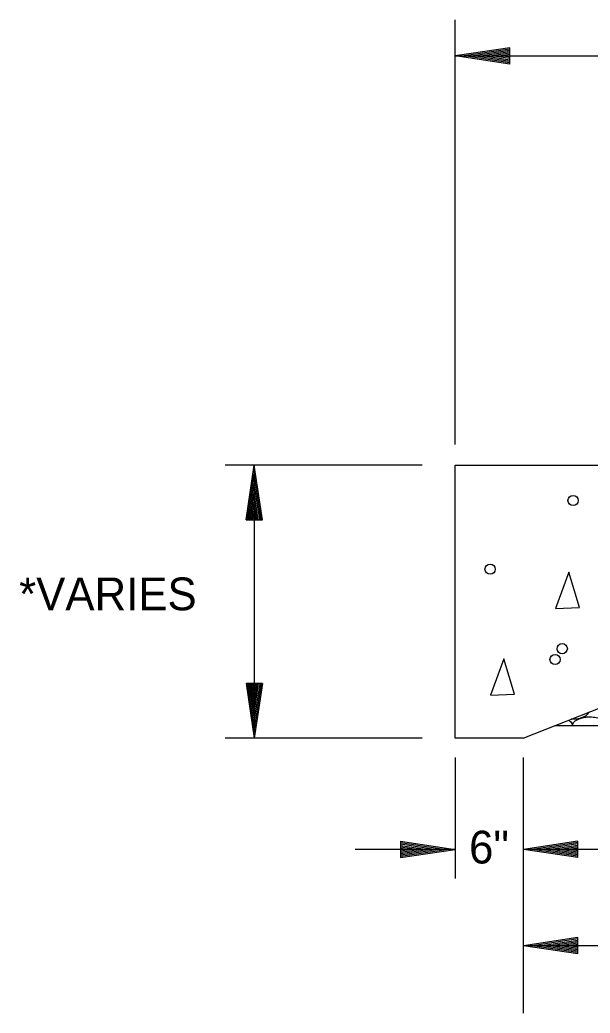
# Model space of a CAD drawing. Extents: x 3287 to 1767681, y -265 to 581440.
# Drawn here: x 3310.56 to 3331.47, y -60.82 to -24.43 of the extents above; entities that cross this region are included whole.
import ezdxf

# ---------------------------------------------------------------- set-up
doc = ezdxf.new("R2010")
doc.units = 0
doc.layers.add('Default', color=7, linetype='Continuous')

msp = doc.modelspace()

# ---------------------------------------------------------------- linework, layer by layer
at = {"layer": 'Default'}
for p, q in [((3326.516, -39.994), (3326.516, -24.434)), ((3328.519, -25.457), (3326.519, -25.757)), ((3328.519, -26.057), (3328.519, -25.457)), ((3326.516, -25.756), (3426.51, -25.756)), ((3328.519, -26.057), (3326.519, -25.757)), ((3328.519, -25.507), (3326.854, -25.757)), ((3328.519, -26.007), (3326.854, -25.757)), ((3328.519, -25.557), (3327.194, -25.757)), ((3328.519, -25.957), (3327.194, -25.757)), ((3328.519, -25.607), (3327.529, -25.757)), ((3328.519, -25.907), (3327.529, -25.757)), ((3328.519, -25.657), (3327.869, -25.757)), ((3328.519, -25.852), (3327.869, -25.757)), ((3328.519, -25.707), (3328.204, -25.757)), ((3328.519, -25.802), (3328.204, -25.757)), ((3325.31, -40.744), (3318.083, -40.744)), ((3318.85, -42.746), (3319.15, -40.747)), ((3319.15, -40.744), (3319.15, -50.743)), ((3319.45, -42.746), (3319.15, -40.747)), ((3326.516, -40.744), (3509.005, -40.744)), ((3326.516, -50.743), (3326.516, -40.744)), ((3318.9, -42.746), (3319.15, -41.076)), ((3319.4, -42.746), (3319.15, -41.076)), ((3318.955, -42.746), (3319.15, -41.421)), ((3319.35, -42.746), (3319.15, -41.421)), ((3319.005, -42.746), (3319.15, -41.756)), ((3319.3, -42.746), (3319.15, -41.756)), ((3319.055, -42.746), (3319.15, -42.096)), ((3319.25, -42.746), (3319.15, -42.096)), ((3319.105, -42.746), (3319.15, -42.426)), ((3319.2, -42.746), (3319.15, -42.426)), ((3318.85, -42.746), (3319.45, -42.746)), ((3329.016, -50.743), (3339.016, -46.785)), ((3318.85, -48.746), (3319.15, -50.746)), ((3319.45, -48.746), (3318.85, -48.746)), ((3318.9, -48.746), (3319.15, -50.411)), ((3318.955, -48.746), (3319.15, -50.066)), ((3319.005, -48.746), (3319.15, -49.731)), ((3319.055, -48.746), (3319.15, -49.396)), ((3319.105, -48.746), (3319.15, -49.061)), ((3319.45, -48.746), (3319.15, -50.746)), ((3319.25, -48.746), (3319.15, -49.396)), ((3319.35, -48.746), (3319.15, -50.066)), ((3319.4, -48.746), (3319.15, -50.411)), ((3319.3, -48.746), (3319.15, -49.731)), ((3319.2, -48.746), (3319.15, -49.061)), ((3331.454, -49.965), (3331.469, -49.965)), ((3330.174, -50.285), (3419.01, -50.285)), ((3325.31, -50.743), (3318.083, -50.743)), ((3329.016, -50.743), (3326.516, -50.743)), ((3326.516, -51.45), (3326.516, -55.887)), ((3329.016, -51.45), (3329.016, -60.817)), ((3324.519, -54.521), (3326.519, -54.821)), ((3324.519, -54.521), (3324.519, -55.121)), ((3324.519, -54.571), (3326.184, -54.821)), ((3331.019, -54.521), (3329.019, -54.821)), ((3331.019, -54.571), (3329.354, -54.821)), ((3331.019, -55.121), (3331.019, -54.521)), ((3326.516, -54.819), (3322.846, -54.819)), ((3324.519, -54.621), (3325.839, -54.821)), ((3324.519, -54.671), (3325.509, -54.821)), ((3324.519, -54.721), (3325.169, -54.821)), ((3324.519, -54.771), (3324.834, -54.821)), ((3324.519, -55.121), (3326.519, -54.821)), ((3324.519, -54.916), (3325.169, -54.821)), ((3324.519, -55.021), (3325.839, -54.821)), ((3324.519, -55.071), (3326.184, -54.821)), ((3324.519, -54.971), (3325.509, -54.821)), ((3324.519, -54.866), (3324.834, -54.821)), ((3332.947, -54.819), (3329.016, -54.819)), ((3331.019, -55.121), (3329.019, -54.821)), ((3331.019, -55.071), (3329.354, -54.821)), ((3331.019, -54.621), (3329.694, -54.821)), ((3331.019, -55.021), (3329.694, -54.821)), ((3331.019, -54.671), (3330.029, -54.821)), ((3331.019, -54.971), (3330.029, -54.821)), ((3331.019, -54.721), (3330.369, -54.821)), ((3331.019, -54.916), (3330.369, -54.821)), ((3331.019, -54.771), (3330.704, -54.821)), ((3331.019, -54.866), (3330.704, -54.821)), ((3331.019, -58.05), (3329.019, -58.35)), ((3331.019, -58.1), (3329.354, -58.35)), ((3331.019, -58.155), (3329.694, -58.35)), ((3331.019, -58.205), (3330.029, -58.35)), ((3331.019, -58.65), (3331.019, -58.05)), ((3339.016, -58.352), (3329.016, -58.352)), ((3331.019, -58.65), (3329.019, -58.35)), ((3331.019, -58.6), (3329.354, -58.35)), ((3331.019, -58.55), (3329.694, -58.35)), ((3331.019, -58.5), (3330.029, -58.35)), ((3331.019, -58.255), (3330.369, -58.35)), ((3331.019, -58.45), (3330.369, -58.35)), ((3331.019, -58.305), (3330.704, -58.35)), ((3331.019, -58.4), (3330.704, -58.35))]:
    msp.add_line(p, q, dxfattribs=at)
for points in [[(3330.684, -44.661), (3330.199, -45.991), (3331.079, -45.956), (3330.684, -44.661)], [(3328.304, -47.841), (3327.819, -49.171), (3328.699, -49.131), (3328.304, -47.841)]]:
    msp.add_lwpolyline(points, dxfattribs=at)
for centre in [(3330.843, -42.038), (3327.799, -44.554), (3330.446, -47.467), (3330.181, -47.864)]:
    msp.add_circle(centre, 0.187, dxfattribs=at)
for points in [[(3331.424, -49.79), (3331.369, -49.875), (3331.294, -49.935), (3331.139, -50.005), (3330.924, -50.05), (3330.814, -50.05), (3330.775, -50.047)], [(3330.676, -50.086), (3330.794, -50.205), (3330.814, -50.28), (3330.814, -50.285)], [(3330.829, -50.285), (3330.829, -50.28), (3330.869, -50.16), (3330.969, -50.08), (3331.069, -50.035), (3331.219, -49.99), (3331.314, -49.97), (3331.454, -49.965)], [(3331.469, -49.965), (3331.689, -49.99), (3331.944, -50.08), (3332.074, -50.205), (3332.094, -50.28), (3332.094, -50.285)]]:
    msp.add_spline(points, degree=3, dxfattribs=at)

# ---------------------------------------------------------------- texts
for s, p in [('*VARIES', (3310.53, -46.06)), ('6"', (3327.029, -55.336))]:
    msp.add_text(s, height=1.2, dxfattribs=at).set_placement(p)

doc.saveas('drawing.dxf')
